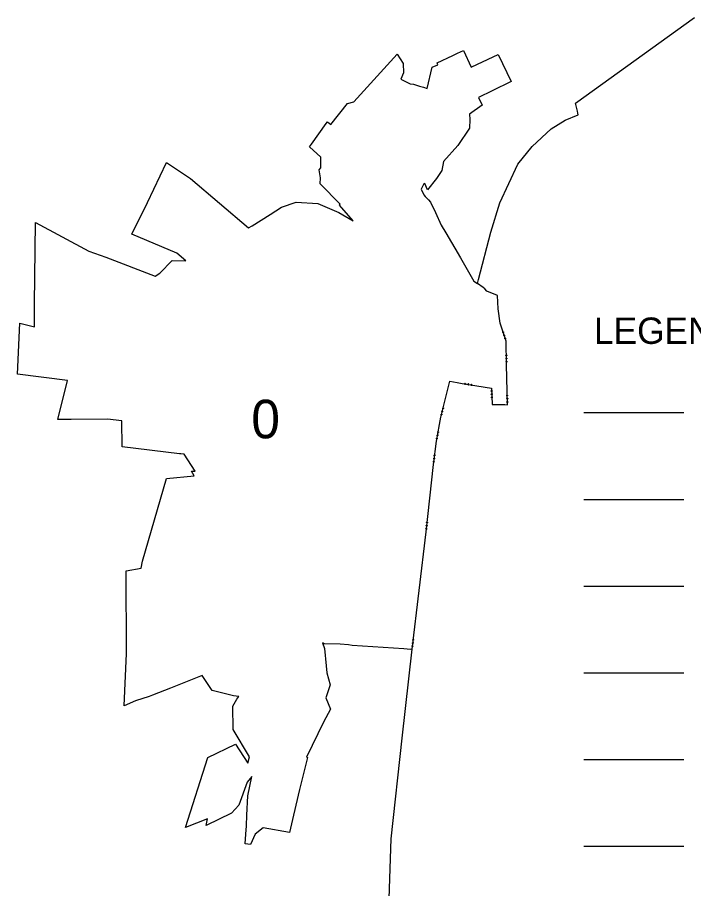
# Model space of a CAD drawing. Extents: x -609574 to -606486, y -1122348 to -1119691.
# Drawn here: x -607797 to -607272, y -1120937 to -1120259 of the extents above; entities that cross this region are included whole.
import ezdxf

# ---------------------------------------------------------------- set-up
doc = ezdxf.new("R2010")
doc.units = 0
for name, color, linetype in [('HRA_OB', 7, 'Continuous'), ('LEGENDA', 7, 'Continuous'), ('OVNE_SET', 7, 'Continuous'), ('POZN', 7, 'Continuous')]:
    doc.layers.add(name, color=color, linetype=linetype)

msp = doc.modelspace()

# ---------------------------------------------------------------- linework, layer by layer
at = {"layer": 'HRA_OB'}
for points in [[(-607490.48, -1120750.66), (-607479.62, -1120659.33), (-607473.93, -1120607.11), (-607471.59, -1120588.97), (-607468.15, -1120570.3), (-607461.05, -1120542.23), (-607455.39, -1120543.18), (-607451.45, -1120543.91), (-607428.71, -1120547.63), (-607428.21, -1120560.41), (-607421.42, -1120560.36), (-607418.34, -1120560.34), (-607416.36, -1120560.59), (-607416.99, -1120529.26), (-607417.35, -1120511), (-607422.06, -1120496.97), (-607423.44, -1120485.9), (-607424.01, -1120475.64), (-607432.23, -1120472.07), (-607433.99, -1120470.4), (-607435.26, -1120469.2), (-607439.72, -1120466.18)], [(-607419.99, -1120504.13), (-607419.87, -1120503.89), (-607419.62, -1120503.81), (-607419.38, -1120503.93), (-607419.29, -1120504.18), (-607419.41, -1120504.42), (-607419.67, -1120504.51), (-607419.91, -1120504.39), (-607419.99, -1120504.13), (-607419.94, -1120504.16), (-607419.87, -1120504.39), (-607419.77, -1120504.42), (-607419.89, -1120504.06), (-607419.84, -1120503.96), (-607419.68, -1120504.45), (-607419.6, -1120504.42), (-607419.77, -1120503.93), (-607419.69, -1120503.91), (-607419.52, -1120504.4), (-607419.44, -1120504.38), (-607419.61, -1120503.89), (-607419.52, -1120503.9), (-607419.39, -1120504.29), (-607419.33, -1120504.22), (-607419.41, -1120503.99)], [(-607419.19, -1120506.51), (-607419.07, -1120506.27), (-607418.82, -1120506.19), (-607418.58, -1120506.31), (-607418.49, -1120506.56), (-607418.61, -1120506.8), (-607418.87, -1120506.89), (-607419.11, -1120506.77), (-607419.19, -1120506.51), (-607419.15, -1120506.51), (-607419.08, -1120506.74), (-607418.97, -1120506.79), (-607419.1, -1120506.41), (-607419.05, -1120506.31), (-607418.87, -1120506.84), (-607418.8, -1120506.81), (-607418.98, -1120506.28), (-607418.9, -1120506.26), (-607418.72, -1120506.79), (-607418.65, -1120506.76), (-607418.82, -1120506.23), (-607418.72, -1120506.28), (-607418.6, -1120506.66), (-607418.55, -1120506.56), (-607418.62, -1120506.33)], [(-607418.39, -1120508.89), (-607418.28, -1120508.65), (-607418.02, -1120508.57), (-607417.78, -1120508.69), (-607417.69, -1120508.94), (-607417.81, -1120509.18), (-607418.07, -1120509.27), (-607418.31, -1120509.15), (-607418.39, -1120508.89), (-607418.36, -1120508.87), (-607418.28, -1120509.1), (-607418.18, -1120509.15), (-607418.31, -1120508.77), (-607418.25, -1120508.69), (-607418.08, -1120509.2), (-607418.01, -1120509.17), (-607418.17, -1120508.67), (-607418.1, -1120508.64), (-607417.93, -1120509.14), (-607417.86, -1120509.11), (-607418.03, -1120508.61), (-607417.93, -1120508.63), (-607417.8, -1120509.04), (-607417.74, -1120508.95), (-607417.83, -1120508.68)], [(-607417.45, -1120521.92), (-607417.27, -1120521.72), (-607417, -1120521.72), (-607416.8, -1120521.9), (-607416.8, -1120522.17), (-607416.99, -1120522.37), (-607417.26, -1120522.37), (-607417.45, -1120522.19), (-607417.45, -1120521.92), (-607417.41, -1120521.96), (-607417.41, -1120522.2), (-607417.33, -1120522.26), (-607417.34, -1120521.88), (-607417.26, -1120521.79), (-607417.25, -1120522.31), (-607417.17, -1120522.31), (-607417.18, -1120521.79), (-607417.1, -1120521.79), (-607417.09, -1120522.31), (-607417.01, -1120522.32), (-607417.02, -1120521.8), (-607416.94, -1120521.84), (-607416.93, -1120522.25), (-607416.85, -1120522.2), (-607416.85, -1120521.96)], [(-607417.41, -1120524.43), (-607417.22, -1120524.23), (-607416.95, -1120524.23), (-607416.76, -1120524.41), (-607416.75, -1120524.68), (-607416.94, -1120524.88), (-607417.21, -1120524.88), (-607417.4, -1120524.7), (-607417.41, -1120524.43), (-607417.37, -1120524.44), (-607417.36, -1120524.68), (-607417.28, -1120524.75), (-607417.29, -1120524.35), (-607417.21, -1120524.27), (-607417.2, -1120524.83), (-607417.12, -1120524.83), (-607417.13, -1120524.27), (-607417.05, -1120524.27), (-607417.04, -1120524.83), (-607416.96, -1120524.83), (-607416.97, -1120524.27), (-607416.89, -1120524.35), (-607416.88, -1120524.75), (-607416.8, -1120524.67), (-607416.81, -1120524.43)], [(-607417.36, -1120526.94), (-607417.17, -1120526.74), (-607416.9, -1120526.74), (-607416.71, -1120526.92), (-607416.7, -1120527.19), (-607416.89, -1120527.39), (-607417.16, -1120527.39), (-607417.35, -1120527.21), (-607417.36, -1120526.94), (-607417.32, -1120526.93), (-607417.31, -1120527.17), (-607417.23, -1120527.24), (-607417.24, -1120526.84), (-607417.16, -1120526.78), (-607417.15, -1120527.32), (-607417.07, -1120527.32), (-607417.08, -1120526.79), (-607417, -1120526.78), (-607416.99, -1120527.31), (-607416.91, -1120527.31), (-607416.92, -1120526.78), (-607416.84, -1120526.83), (-607416.83, -1120527.26), (-607416.75, -1120527.18), (-607416.76, -1120526.9)], [(-607449.1, -1120543.97), (-607448.94, -1120544.19), (-607448.99, -1120544.45), (-607449.2, -1120544.61), (-607449.47, -1120544.57), (-607449.63, -1120544.35), (-607449.58, -1120544.08), (-607449.37, -1120543.93), (-607449.1, -1120543.97), (-607449.1, -1120544.01), (-607449.33, -1120543.97), (-607449.42, -1120544.04), (-607449.03, -1120544.1), (-607448.98, -1120544.19), (-607449.52, -1120544.1), (-607449.53, -1120544.18), (-607449.01, -1120544.27), (-607449.01, -1120544.35), (-607449.53, -1120544.26), (-607449.54, -1120544.34), (-607449.02, -1120544.43), (-607449.08, -1120544.5), (-607449.51, -1120544.43), (-607449.45, -1120544.52), (-607449.18, -1120544.57)], [(-607446.62, -1120544.38), (-607446.46, -1120544.59), (-607446.51, -1120544.86), (-607446.73, -1120545.02), (-607446.99, -1120544.97), (-607447.15, -1120544.76), (-607447.11, -1120544.49), (-607446.89, -1120544.33), (-607446.62, -1120544.38), (-607446.64, -1120544.41), (-607446.88, -1120544.37), (-607446.97, -1120544.44), (-607446.57, -1120544.51), (-607446.51, -1120544.6), (-607447.06, -1120544.51), (-607447.07, -1120544.59), (-607446.52, -1120544.68), (-607446.53, -1120544.76), (-607447.08, -1120544.66), (-607447.1, -1120544.74), (-607446.54, -1120544.83), (-607446.64, -1120544.9), (-607447.03, -1120544.84), (-607446.97, -1120544.93), (-607446.73, -1120544.97)], [(-607444.14, -1120544.78), (-607443.99, -1120545), (-607444.03, -1120545.27), (-607444.25, -1120545.42), (-607444.52, -1120545.38), (-607444.67, -1120545.16), (-607444.63, -1120544.89), (-607444.41, -1120544.74), (-607444.14, -1120544.78), (-607444.19, -1120544.81), (-607444.43, -1120544.78), (-607444.5, -1120544.84), (-607444.12, -1120544.91), (-607444.06, -1120545), (-607444.57, -1120544.91), (-607444.58, -1120544.99), (-607444.07, -1120545.08), (-607444.08, -1120545.16), (-607444.6, -1120545.07), (-607444.62, -1120545.15), (-607444.11, -1120545.23), (-607444.16, -1120545.31), (-607444.56, -1120545.24), (-607444.53, -1120545.33), (-607444.29, -1120545.36)], [(-607428.3, -1120549.95), (-607428.48, -1120550.14), (-607428.75, -1120550.15), (-607428.95, -1120549.97), (-607428.96, -1120549.7), (-607428.78, -1120549.5), (-607428.51, -1120549.49), (-607428.31, -1120549.68), (-607428.3, -1120549.95), (-607428.34, -1120549.96), (-607428.35, -1120549.72), (-607428.43, -1120549.64), (-607428.42, -1120550.04), (-607428.49, -1120550.1), (-607428.51, -1120549.56), (-607428.59, -1120549.57), (-607428.57, -1120550.1), (-607428.65, -1120550.11), (-607428.67, -1120549.58), (-607428.75, -1120549.58), (-607428.73, -1120550.11), (-607428.81, -1120550.07), (-607428.83, -1120549.64), (-607428.91, -1120549.71), (-607428.9, -1120549.99)], [(-607428.2, -1120552.45), (-607428.38, -1120552.65), (-607428.65, -1120552.66), (-607428.85, -1120552.48), (-607428.86, -1120552.21), (-607428.68, -1120552.01), (-607428.41, -1120552), (-607428.21, -1120552.18), (-607428.2, -1120552.45), (-607428.24, -1120552.45), (-607428.25, -1120552.21), (-607428.33, -1120552.13), (-607428.32, -1120552.53), (-607428.4, -1120552.61), (-607428.42, -1120552.05), (-607428.5, -1120552.06), (-607428.47, -1120552.61), (-607428.55, -1120552.62), (-607428.58, -1120552.06), (-607428.66, -1120552.06), (-607428.63, -1120552.62), (-607428.72, -1120552.54), (-607428.73, -1120552.14), (-607428.81, -1120552.23), (-607428.8, -1120552.47)], [(-607416.83, -1120553.25), (-607416.64, -1120553.05), (-607416.37, -1120553.05), (-607416.18, -1120553.23), (-607416.17, -1120553.5), (-607416.36, -1120553.7), (-607416.63, -1120553.7), (-607416.82, -1120553.52), (-607416.83, -1120553.25), (-607416.79, -1120553.29), (-607416.78, -1120553.53), (-607416.7, -1120553.59), (-607416.71, -1120553.21), (-607416.63, -1120553.12), (-607416.62, -1120553.64), (-607416.54, -1120553.64), (-607416.55, -1120553.12), (-607416.47, -1120553.12), (-607416.46, -1120553.64), (-607416.38, -1120553.65), (-607416.39, -1120553.13), (-607416.31, -1120553.17), (-607416.3, -1120553.58), (-607416.22, -1120553.53), (-607416.23, -1120553.29)], [(-607428.1, -1120554.96), (-607428.29, -1120555.16), (-607428.56, -1120555.17), (-607428.75, -1120554.99), (-607428.76, -1120554.72), (-607428.58, -1120554.52), (-607428.31, -1120554.51), (-607428.11, -1120554.69), (-607428.1, -1120554.96), (-607428.14, -1120554.92), (-607428.15, -1120554.68), (-607428.24, -1120554.63), (-607428.22, -1120555.01), (-607428.3, -1120555.09), (-607428.32, -1120554.57), (-607428.4, -1120554.57), (-607428.38, -1120555.09), (-607428.46, -1120555.1), (-607428.48, -1120554.58), (-607428.56, -1120554.57), (-607428.54, -1120555.09), (-607428.62, -1120555.05), (-607428.64, -1120554.64), (-607428.71, -1120554.7), (-607428.7, -1120554.94)], [(-607416.78, -1120555.76), (-607416.59, -1120555.56), (-607416.32, -1120555.56), (-607416.13, -1120555.74), (-607416.12, -1120556.01), (-607416.31, -1120556.21), (-607416.58, -1120556.21), (-607416.77, -1120556.03), (-607416.78, -1120555.76), (-607416.74, -1120555.77), (-607416.73, -1120556.01), (-607416.65, -1120556.08), (-607416.66, -1120555.69), (-607416.58, -1120555.6), (-607416.57, -1120556.16), (-607416.49, -1120556.16), (-607416.5, -1120555.6), (-607416.42, -1120555.6), (-607416.41, -1120556.16), (-607416.33, -1120556.16), (-607416.34, -1120555.6), (-607416.26, -1120555.68), (-607416.25, -1120556.08), (-607416.17, -1120556), (-607416.18, -1120555.76)], [(-607416.73, -1120558.27), (-607416.54, -1120558.07), (-607416.27, -1120558.07), (-607416.08, -1120558.25), (-607416.07, -1120558.52), (-607416.26, -1120558.72), (-607416.53, -1120558.72), (-607416.72, -1120558.54), (-607416.73, -1120558.27), (-607416.69, -1120558.26), (-607416.68, -1120558.5), (-607416.6, -1120558.57), (-607416.61, -1120558.17), (-607416.53, -1120558.11), (-607416.52, -1120558.65), (-607416.44, -1120558.65), (-607416.45, -1120558.12), (-607416.37, -1120558.11), (-607416.36, -1120558.64), (-607416.28, -1120558.64), (-607416.29, -1120558.11), (-607416.21, -1120558.16), (-607416.2, -1120558.59), (-607416.12, -1120558.51), (-607416.13, -1120558.23)], [(-607467.27, -1120565.53), (-607467.04, -1120565.39), (-607466.78, -1120565.46), (-607466.64, -1120565.69), (-607466.71, -1120565.95), (-607466.94, -1120566.09), (-607467.2, -1120566.02), (-607467.34, -1120565.79), (-607467.27, -1120565.53), (-607467.24, -1120565.55), (-607467.3, -1120565.78), (-607467.24, -1120565.88), (-607467.14, -1120565.49), (-607467.04, -1120565.43), (-607467.18, -1120565.98), (-607467.1, -1120566), (-607466.97, -1120565.45), (-607466.89, -1120565.47), (-607467.02, -1120566.02), (-607466.95, -1120566.03), (-607466.81, -1120565.49), (-607466.75, -1120565.59), (-607466.85, -1120565.98), (-607466.75, -1120565.92), (-607466.69, -1120565.69)], [(-607466.66, -1120563.1), (-607466.43, -1120562.96), (-607466.17, -1120563.02), (-607466.03, -1120563.26), (-607466.09, -1120563.52), (-607466.32, -1120563.65), (-607466.59, -1120563.59), (-607466.72, -1120563.36), (-607466.66, -1120563.1), (-607466.63, -1120563.14), (-607466.69, -1120563.38), (-607466.62, -1120563.45), (-607466.53, -1120563.09), (-607466.43, -1120563.03), (-607466.56, -1120563.53), (-607466.48, -1120563.55), (-607466.36, -1120563.05), (-607466.28, -1120563.07), (-607466.41, -1120563.57), (-607466.33, -1120563.6), (-607466.2, -1120563.1), (-607466.14, -1120563.16), (-607466.24, -1120563.55), (-607466.15, -1120563.52), (-607466.09, -1120563.29)], [(-607467.89, -1120567.96), (-607467.66, -1120567.83), (-607467.4, -1120567.89), (-607467.26, -1120568.12), (-607467.32, -1120568.38), (-607467.56, -1120568.52), (-607467.82, -1120568.46), (-607467.96, -1120568.22), (-607467.89, -1120567.96), (-607467.85, -1120567.96), (-607467.91, -1120568.2), (-607467.85, -1120568.29), (-607467.75, -1120567.9), (-607467.66, -1120567.87), (-607467.79, -1120568.39), (-607467.71, -1120568.41), (-607467.58, -1120567.9), (-607467.5, -1120567.91), (-607467.63, -1120568.42), (-607467.56, -1120568.44), (-607467.43, -1120567.93), (-607467.36, -1120567.99), (-607467.47, -1120568.41), (-607467.37, -1120568.36), (-607467.3, -1120568.09)], [(-607471.48, -1120586.62), (-607471.26, -1120586.47), (-607471, -1120586.52), (-607470.84, -1120586.74), (-607470.89, -1120587), (-607471.11, -1120587.16), (-607471.38, -1120587.11), (-607471.53, -1120586.89), (-607471.48, -1120586.62), (-607471.44, -1120586.62), (-607471.48, -1120586.85), (-607471.42, -1120586.95), (-607471.35, -1120586.55), (-607471.26, -1120586.51), (-607471.36, -1120587.04), (-607471.28, -1120587.05), (-607471.18, -1120586.53), (-607471.1, -1120586.54), (-607471.2, -1120587.06), (-607471.12, -1120587.07), (-607471.02, -1120586.55), (-607470.95, -1120586.62), (-607471.03, -1120587.04), (-607470.94, -1120586.99), (-607470.89, -1120586.71)], [(-607471.03, -1120584.15), (-607470.81, -1120584), (-607470.54, -1120584.05), (-607470.39, -1120584.27), (-607470.44, -1120584.54), (-607470.66, -1120584.69), (-607470.92, -1120584.64), (-607471.08, -1120584.42), (-607471.03, -1120584.15), (-607470.99, -1120584.17), (-607471.03, -1120584.41), (-607470.97, -1120584.5), (-607470.9, -1120584.11), (-607470.8, -1120584.04), (-607470.91, -1120584.59), (-607470.83, -1120584.61), (-607470.73, -1120584.06), (-607470.65, -1120584.07), (-607470.75, -1120584.62), (-607470.67, -1120584.64), (-607470.57, -1120584.08), (-607470.5, -1120584.18), (-607470.58, -1120584.57), (-607470.48, -1120584.51), (-607470.44, -1120584.27)], [(-607470.57, -1120581.68), (-607470.35, -1120581.53), (-607470.09, -1120581.58), (-607469.93, -1120581.8), (-607469.98, -1120582.07), (-607470.2, -1120582.22), (-607470.47, -1120582.17), (-607470.62, -1120581.95), (-607470.57, -1120581.68), (-607470.54, -1120581.73), (-607470.58, -1120581.97), (-607470.52, -1120582.04), (-607470.45, -1120581.67), (-607470.35, -1120581.6), (-607470.45, -1120582.11), (-607470.37, -1120582.13), (-607470.28, -1120581.62), (-607470.2, -1120581.63), (-607470.29, -1120582.14), (-607470.21, -1120582.17), (-607470.12, -1120581.66), (-607470.05, -1120581.71), (-607470.12, -1120582.11), (-607470.04, -1120582.08), (-607469.99, -1120581.84)], [(-607473.31, -1120599.78), (-607473.09, -1120599.62), (-607472.83, -1120599.65), (-607472.66, -1120599.86), (-607472.7, -1120600.13), (-607472.91, -1120600.29), (-607473.18, -1120600.26), (-607473.34, -1120600.05), (-607473.31, -1120599.78), (-607473.27, -1120599.82), (-607473.3, -1120600.06), (-607473.23, -1120600.13), (-607473.18, -1120599.76), (-607473.09, -1120599.69), (-607473.16, -1120600.2), (-607473.08, -1120600.21), (-607473.01, -1120599.7), (-607472.93, -1120599.71), (-607473, -1120600.22), (-607472.92, -1120600.24), (-607472.86, -1120599.73), (-607472.78, -1120599.78), (-607472.83, -1120600.18), (-607472.75, -1120600.14), (-607472.72, -1120599.91)], [(-607473.95, -1120604.76), (-607473.74, -1120604.59), (-607473.47, -1120604.63), (-607473.3, -1120604.84), (-607473.34, -1120605.11), (-607473.55, -1120605.27), (-607473.82, -1120605.24), (-607473.98, -1120605.03), (-607473.95, -1120604.76), (-607473.91, -1120604.75), (-607473.94, -1120604.99), (-607473.87, -1120605.08), (-607473.82, -1120604.68), (-607473.73, -1120604.64), (-607473.8, -1120605.17), (-607473.72, -1120605.18), (-607473.65, -1120604.66), (-607473.57, -1120604.66), (-607473.64, -1120605.18), (-607473.56, -1120605.19), (-607473.49, -1120604.67), (-607473.42, -1120604.73), (-607473.48, -1120605.15), (-607473.39, -1120605.09), (-607473.35, -1120604.82)], [(-607473.63, -1120602.27), (-607473.42, -1120602.1), (-607473.15, -1120602.14), (-607472.98, -1120602.35), (-607473.02, -1120602.62), (-607473.23, -1120602.78), (-607473.5, -1120602.75), (-607473.66, -1120602.54), (-607473.63, -1120602.27), (-607473.59, -1120602.28), (-607473.62, -1120602.52), (-607473.55, -1120602.61), (-607473.5, -1120602.21), (-607473.41, -1120602.15), (-607473.48, -1120602.7), (-607473.4, -1120602.71), (-607473.33, -1120602.16), (-607473.25, -1120602.17), (-607473.32, -1120602.72), (-607473.24, -1120602.73), (-607473.17, -1120602.18), (-607473.1, -1120602.27), (-607473.15, -1120602.66), (-607473.07, -1120602.59), (-607473.03, -1120602.36)], [(-607479.41, -1120654.48), (-607479.2, -1120654.32), (-607478.94, -1120654.34), (-607478.77, -1120654.55), (-607478.8, -1120654.82), (-607479.01, -1120654.99), (-607479.27, -1120654.96), (-607479.44, -1120654.75), (-607479.41, -1120654.48), (-607479.38, -1120654.5), (-607479.4, -1120654.74), (-607479.33, -1120654.82), (-607479.29, -1120654.43), (-607479.2, -1120654.36), (-607479.26, -1120654.91), (-607479.18, -1120654.92), (-607479.12, -1120654.37), (-607479.04, -1120654.37), (-607479.1, -1120654.93), (-607479.02, -1120654.94), (-607478.96, -1120654.38), (-607478.89, -1120654.47), (-607478.93, -1120654.87), (-607478.84, -1120654.8), (-607478.82, -1120654.56)], [(-607479.14, -1120651.99), (-607478.93, -1120651.82), (-607478.66, -1120651.85), (-607478.5, -1120652.06), (-607478.53, -1120652.33), (-607478.73, -1120652.5), (-607479, -1120652.47), (-607479.17, -1120652.26), (-607479.14, -1120651.99), (-607479.11, -1120652.03), (-607479.13, -1120652.27), (-607479.06, -1120652.34), (-607479.02, -1120651.96), (-607478.93, -1120651.89), (-607478.99, -1120652.41), (-607478.91, -1120652.42), (-607478.85, -1120651.9), (-607478.77, -1120651.91), (-607478.83, -1120652.43), (-607478.75, -1120652.44), (-607478.69, -1120651.93), (-607478.62, -1120651.98), (-607478.66, -1120652.38), (-607478.58, -1120652.34), (-607478.55, -1120652.1)], [(-607479.69, -1120656.98), (-607479.48, -1120656.81), (-607479.21, -1120656.84), (-607479.04, -1120657.05), (-607479.07, -1120657.32), (-607479.28, -1120657.49), (-607479.55, -1120657.46), (-607479.71, -1120657.25), (-607479.69, -1120656.98), (-607479.64, -1120656.97), (-607479.67, -1120657.21), (-607479.6, -1120657.3), (-607479.56, -1120656.9), (-607479.47, -1120656.85), (-607479.53, -1120657.39), (-607479.45, -1120657.4), (-607479.39, -1120656.87), (-607479.31, -1120656.87), (-607479.37, -1120657.4), (-607479.29, -1120657.4), (-607479.23, -1120656.88), (-607479.16, -1120656.94), (-607479.2, -1120657.36), (-607479.12, -1120657.3), (-607479.09, -1120657.02)], [(-607489.93, -1120743.32), (-607489.72, -1120743.16), (-607489.45, -1120743.19), (-607489.28, -1120743.4), (-607489.32, -1120743.67), (-607489.53, -1120743.83), (-607489.8, -1120743.8), (-607489.96, -1120743.59), (-607489.93, -1120743.32), (-607489.89, -1120743.37), (-607489.92, -1120743.61), (-607489.85, -1120743.68), (-607489.81, -1120743.3), (-607489.72, -1120743.23), (-607489.78, -1120743.74), (-607489.7, -1120743.75), (-607489.64, -1120743.24), (-607489.56, -1120743.25), (-607489.62, -1120743.76), (-607489.54, -1120743.78), (-607489.48, -1120743.27), (-607489.41, -1120743.32), (-607489.45, -1120743.72), (-607489.37, -1120743.68), (-607489.34, -1120743.44)], [(-607490.52, -1120748.31), (-607490.31, -1120748.14), (-607490.04, -1120748.17), (-607489.88, -1120748.39), (-607489.91, -1120748.65), (-607490.12, -1120748.82), (-607490.39, -1120748.79), (-607490.55, -1120748.58), (-607490.52, -1120748.31), (-607490.48, -1120748.3), (-607490.51, -1120748.54), (-607490.44, -1120748.63), (-607490.39, -1120748.23), (-607490.31, -1120748.18), (-607490.37, -1120748.72), (-607490.29, -1120748.73), (-607490.23, -1120748.2), (-607490.15, -1120748.2), (-607490.21, -1120748.73), (-607490.13, -1120748.74), (-607490.07, -1120748.21), (-607489.99, -1120748.27), (-607490.05, -1120748.7), (-607489.96, -1120748.64), (-607489.92, -1120748.36)], [(-607490.23, -1120745.82), (-607490.02, -1120745.65), (-607489.75, -1120745.68), (-607489.58, -1120745.89), (-607489.61, -1120746.16), (-607489.82, -1120746.33), (-607490.09, -1120746.3), (-607490.26, -1120746.08), (-607490.23, -1120745.82), (-607490.19, -1120745.83), (-607490.22, -1120746.07), (-607490.15, -1120746.16), (-607490.1, -1120745.76), (-607490.01, -1120745.69), (-607490.08, -1120746.25), (-607490, -1120746.26), (-607489.93, -1120745.7), (-607489.85, -1120745.71), (-607489.92, -1120746.27), (-607489.84, -1120746.28), (-607489.77, -1120745.72), (-607489.7, -1120745.81), (-607489.75, -1120746.21), (-607489.66, -1120746.14), (-607489.63, -1120745.9)]]:
    msp.add_lwpolyline(points, dxfattribs=at)
at = {"layer": 'LEGENDA'}
for points in [[(-607357.02, -1120566.68), (-607279.02, -1120566.68)], [(-607357.02, -1120634.18), (-607279.02, -1120634.18)], [(-607357.02, -1120701.68), (-607279.02, -1120701.68)], [(-607357.02, -1120769.18), (-607279.02, -1120769.18)], [(-607357.02, -1120836.68), (-607279.02, -1120836.68)], [(-607357.02, -1120904.18), (-607279.02, -1120904.18)]]:
    msp.add_lwpolyline(points, dxfattribs=at)
at = {"layer": 'OVNE_SET'}
msp.add_lwpolyline([(-607510, -1120999.04), (-607506.66, -1120898.26), (-607498.29, -1120820.05), (-607490.48, -1120750.66), (-607491.8, -1120750.99), (-607496.99, -1120750.64), (-607536.96, -1120747.79), (-607539.8, -1120747.45), (-607546.37, -1120746.96), (-607558.79, -1120746.59), (-607560.19, -1120745.86), (-607558.63, -1120750.38), (-607557.32, -1120763.62), (-607556.75, -1120769.29), (-607554.3, -1120778.45), (-607557.53, -1120788.59), (-607553.87, -1120797.43), (-607559.47, -1120807.59), (-607572.71, -1120834.7), (-607571.86, -1120835.03), (-607578.07, -1120859.97), (-607582.64, -1120879.84), (-607585.8, -1120893.55), (-607606.22, -1120889.73), (-607612.63, -1120894.64), (-607616.02, -1120902.73), (-607620.19, -1120902.21), (-607619.69, -1120894.71), (-607619.26, -1120888.26), (-607618.94, -1120880), (-607618.09, -1120864.9), (-607615.1, -1120849.83), (-607618.67, -1120854.34), (-607625.21, -1120872.23), (-607630.89, -1120878.34), (-607650.53, -1120887.94), (-607649.59, -1120882.78), (-607666.74, -1120889.64), (-607649.45, -1120835.15), (-607627.72, -1120824.72), (-607618.23, -1120839.55), (-607617, -1120834.63), (-607629.59, -1120813.29), (-607629.85, -1120795.23), (-607626.67, -1120789.67), (-607625.19, -1120787.66), (-607629.4, -1120786.99), (-607645.89, -1120782.92), (-607653.72, -1120771.27), (-607678.32, -1120781), (-607692.43, -1120786.59), (-607694.84, -1120787.54), (-607705.57, -1120790.85), (-607714.31, -1120794.83), (-607712.67, -1120754.04), (-607712.73, -1120689.93), (-607701.19, -1120687.62), (-607700.14, -1120682.41), (-607690.82, -1120650.2), (-607681.46, -1120617.88), (-607659.92, -1120615.78), (-607661.93, -1120612.3), (-607659.23, -1120612.22), (-607667.76, -1120599.12), (-607670.2, -1120598.82), (-607671.32, -1120598.68), (-607716.06, -1120593.18), (-607716.16, -1120573.18), (-607727.43, -1120571.83), (-607755.56, -1120571.91), (-607766.07, -1120571.93), (-607758.46, -1120541.75), (-607797.4, -1120536.66), (-607795.44, -1120497.16), (-607784.24, -1120499.84), (-607784.04, -1120481.95), (-607783.81, -1120460.98), (-607783.34, -1120418.6), (-607741.91, -1120441.02), (-607728.59, -1120445.74), (-607690.36, -1120460.55), (-607686.65, -1120458.23), (-607676.97, -1120448.4), (-607666.41, -1120448.44), (-607673.32, -1120442.56), (-607708.32, -1120427.85), (-607696.32, -1120403.21), (-607681.37, -1120372.16), (-607662.68, -1120384.37), (-607617.63, -1120422.81), (-607614.83, -1120421.3), (-607600.73, -1120412.48), (-607591.99, -1120406.67), (-607580.62, -1120402.94), (-607563.75, -1120404.07), (-607547.36, -1120410.93), (-607536.23, -1120417.48), (-607547.05, -1120405.29), (-607546.29, -1120404.52), (-607562.03, -1120388.64), (-607561.73, -1120383.88), (-607562.83, -1120377.65), (-607561.56, -1120376.14), (-607561.56, -1120367.93), (-607570.37, -1120359.77), (-607568.6, -1120357.86), (-607557.19, -1120341.68), (-607556.25, -1120340.35), (-607553.54, -1120342.36), (-607540.81, -1120326.08), (-607535.69, -1120324.72), (-607502.03, -1120287.78), (-607497.48, -1120295.03), (-607497.14, -1120302.27), (-607499.11, -1120307.12), (-607491.89, -1120310.81), (-607489.31, -1120311.14), (-607484.77, -1120312.62), (-607481.68, -1120313.51), (-607478.8, -1120314.34), (-607474.92, -1120297.72), (-607470.38, -1120295.98), (-607471.02, -1120294.46), (-607458.69, -1120288.66), (-607455.08, -1120286.84), (-607450.55, -1120284.83), (-607444.41, -1120297.86), (-607439.62, -1120295.57), (-607423.48, -1120287.92), (-607413.52, -1120308.99), (-607428.12, -1120316.36), (-607438.92, -1120321.57), (-607436.01, -1120327.42), (-607445.9, -1120334.4), (-607445.6, -1120338.66), (-607445.86, -1120345.43), (-607454.85, -1120358.72), (-607466.09, -1120371.36), (-607467.41, -1120378.2), (-607471.38, -1120384.52), (-607478.49, -1120393.19), (-607480.6, -1120388.27), (-607481.5, -1120389.12), (-607483.36, -1120392.77), (-607481.44, -1120397.21), (-607480.2, -1120398.53), (-607477.69, -1120401.18), (-607476.17, -1120402.79), (-607472.39, -1120410.97), (-607467.91, -1120420.68), (-607464.35, -1120426.71), (-607452.92, -1120446.12), (-607442.52, -1120464.49), (-607439.72, -1120466.18), (-607438.82, -1120463.02), (-607429.25, -1120426.14), (-607422.32, -1120403.44), (-607408.31, -1120373.21), (-607397.01, -1120359.46), (-607382.21, -1120345.82), (-607371.41, -1120339), (-607361.29, -1120334.83), (-607361.57, -1120333.61), (-607361.93, -1120332.06), (-607363.35, -1120325.97), (-607270.8, -1120259.13)], dxfattribs=at)

# ---------------------------------------------------------------- texts
at = {"layer": 'LEGENDA'}
msp.add_text('LEGENDA', height=20.5, dxfattribs=at).set_placement((-607349.02, -1120513.18))
at = {"layer": 'POZN'}
msp.add_text('0', height=30, dxfattribs=at).set_placement((-607615.52, -1120586.67))

doc.saveas('drawing.dxf')
